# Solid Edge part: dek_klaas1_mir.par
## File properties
Author: Mac
Last saved by: Mac
Revision: 55
Accuracy: 0,990
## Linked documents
dek_klaas1.par
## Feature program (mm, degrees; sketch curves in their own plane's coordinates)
part copy "CopiedPart_1"
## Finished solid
Body 1: solid body, 6 faces, 12 edges, 8 vertices.
  Faces by surface: plane 3, offset 1, spline 1, swept 1
  Edges by curve: intersection 7, line 4, curve on surface 1
Bounding box of the edges (mm; curved faces can reach further): 25.859 x 0.701 x 11.978, from (-32.1251, -30.0896, 3.4307) to (-6.2658, -29.3886, 15.4083).
Planar faces by outward normal: -x 1, -z 1, oblique 1
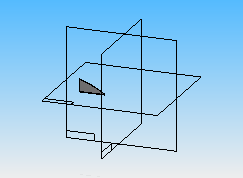
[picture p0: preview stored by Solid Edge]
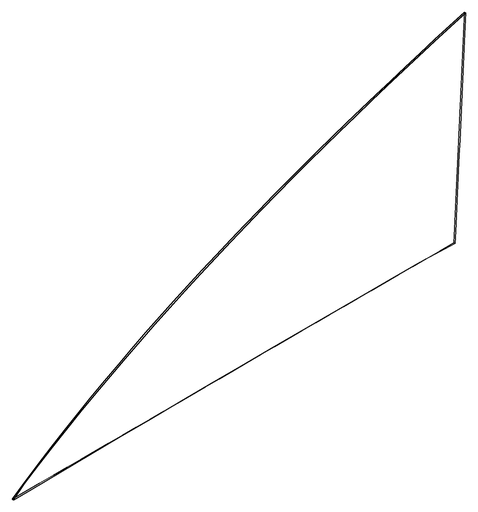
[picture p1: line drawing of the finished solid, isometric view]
